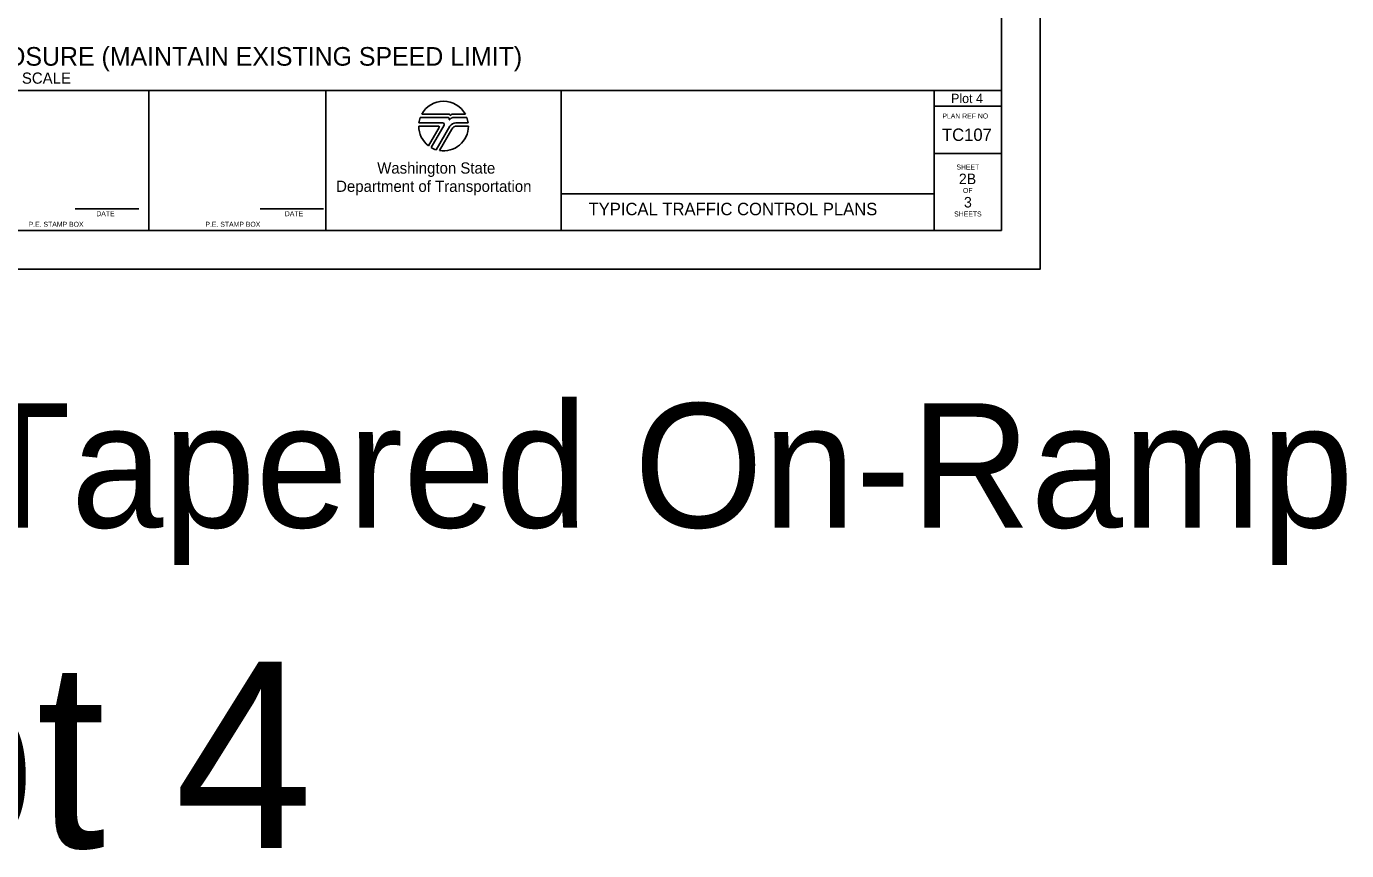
# Model space of a CAD drawing. Extents: x 99999 to 100116, y 99995 to 100013.
# Drawn here: x 100067.9 to 100078.53, y 99995.01 to 100001.64 of the extents above; entities that cross this region are included whole.
import ezdxf

# ---------------------------------------------------------------- set-up
doc = ezdxf.new("R2010")
doc.units = 0
for name, color, linetype in [('SH_DE_DetailHeading1Text', 7, 'Continuous'), ('SH_GI_PlotLimits', 7, 'Continuous'), ('SH_GI_SheetBorder', 7, 'Continuous'), ('SH_GI_SheetLocationText', 7, 'Continuous'), ('SH_GI_SheetTextInCells', 7, 'Continuous'), ('SH_GI_TitleBlockText', 7, 'Continuous'), ('SH_GI_WSDOTLogo', 7, 'Continuous')]:
    doc.layers.add(name, color=color, linetype=linetype)

msp = doc.modelspace()

# ---------------------------------------------------------------- linework, layer by layer
at = {"layer": 'SH_GI_PlotLimits'}
msp.add_lwpolyline([(100059.062, 99999.687), (100076.062, 99999.687), (100076.062, 100010.687), (100059.062, 100010.687)], close=True, dxfattribs=at)
at = {"layer": 'SH_GI_SheetBorder'}
for p, q in [((100075.75, 100010.375), (100075.75, 100000)), ((100060, 100001.126), (100075.75, 100001.126)), ((100068.883, 100000), (100068.883, 100001.126)), ((100070.309, 100001.126), (100070.309, 100000)), ((100072.205, 100001.126), (100072.205, 100000)), ((100075.208, 100001.126), (100075.208, 100000)), ((100075.208, 100001.001), (100075.75, 100001.001)), ((100075.208, 100000.618), (100075.75, 100000.618)), ((100072.205, 100000.295), (100075.208, 100000.295)), ((100068.29, 100000.173), (100068.802, 100000.173)), ((100069.78, 100000.173), (100070.291, 100000.173)), ((100060, 100000), (100075.75, 100000))]:
    msp.add_line(p, q, dxfattribs=at)
at = {"layer": 'SH_GI_WSDOTLogo'}
for p, q in [((100071.303, 100000.935), (100071.081, 100000.935)), ((100071.433, 100000.935), (100071.335, 100000.935)), ((100071.057, 100000.84), (100071.215, 100000.84)), ((100071.059, 100000.866), (100071.25, 100000.866)), ((100071.289, 100000.909), (100071.07, 100000.909)), ((100071.222, 100000.828), (100071.136, 100000.681)), ((100071.261, 100000.846), (100071.157, 100000.667)), ((100071.199, 100000.649), (100071.309, 100000.839)), ((100071.445, 100000.909), (100071.343, 100000.909)), ((100071.343, 100000.909), (100071.343, 100000.909)), ((100071.356, 100000.866), (100071.456, 100000.866)), ((100071.365, 100000.839), (100071.457, 100000.839)), ((100071.224, 100000.643), (100071.324, 100000.816))]:
    msp.add_line(p, q, dxfattribs=at)
for centre, radius, start, end in [((100071.257, 100000.84), 0.2, 28.4787, 151.532), ((100071.303, 100000.926), 0.00903, 329.8742, 90.0033), ((100071.335, 100000.907), 0.0287, 90.0072, 148.1676), ((100071.257, 100000.84), 0.2, 179.9986, 232.8433), ((100071.257, 100000.84), 0.2, 159.696, 172.5057), ((100071.215, 100000.832), 0.0082, 329.7436, 90), ((100071.257, 100000.84), 0.2, 260.5455, 359.8086), ((100071.25, 100000.853), 0.0131, 329.7683, 90), ((100071.289, 100000.895), 0.0148, 327.8418, 89.9985), ((100071.343, 100000.861), 0.0484, 89.9953, 147.8238), ((100071.356, 100000.812), 0.0542, 90, 149.9974), ((100071.365, 100000.792), 0.0476, 90, 150.0543), ((100071.257, 100000.84), 0.2, 7.4943, 20.2941), ((100071.257, 100000.84), 0.2, 239.7929, 253.0448)]:
    msp.add_arc(centre, radius, start, end, dxfattribs=at)

# ---------------------------------------------------------------- texts
at = {"layer": 'SH_DE_DetailHeading1Text'}
for s, height, p in [('FREEWAY (2+ LANES): SINGLE RIGHT LANE CLOSURE (MAINTAIN EXISTING SPEED LIMIT)', 0.15, (100063.191, 100001.326)), ('NOT TO SCALE', 0.09, (100067.373, 100001.181))]:
    msp.add_text(s, height=height, rotation=360, dxfattribs=at).set_placement(p)
at = {"layer": 'SH_GI_SheetBorder'}
msp.add_text('PLAN REF NO', height=0.04003, dxfattribs=at).set_placement((100075.275, 100000.901))
at = {"layer": 'SH_GI_SheetLocationText'}
for s, height, p in [('Plot 4', 0.075, (100075.345, 100001.025)), ('Right Ramps: Tapered On-Ramp', 1, (100058.967, 99997.607)), ('Plot 4', 1.5, (100065.077, 99995.027))]:
    msp.add_text(s, height=height, dxfattribs=at).set_placement(p)
at = {"layer": 'SH_GI_SheetTextInCells'}
for s, height, p in [('Washington State', 0.09007, (100070.723, 100000.457)), ('SHEET', 0.04, (100075.388, 100000.49)), ('Department of Transportation', 0.09007, (100070.392, 100000.31)), ('OF', 0.04, (100075.441, 100000.301)), ('DATE', 0.04, (100068.46, 100000.114)), ('DATE', 0.04, (100069.979, 100000.114)), ('SHEETS', 0.04, (100075.37, 100000.112)), ('P.E. STAMP BOX', 0.04003, (100067.915, 100000.029)), ('P.E. STAMP BOX', 0.04003, (100069.339, 100000.029))]:
    msp.add_text(s, height=height, dxfattribs=at).set_placement(p)
at = {"layer": 'SH_GI_TitleBlockText'}
for s, height, p in [('TC107', 0.1, (100075.272, 100000.72)), ('2B', 0.085, (100075.408, 100000.372)), ('TYPICAL TRAFFIC CONTROL PLANS', 0.1, (100072.425, 100000.122)), ('3', 0.085, (100075.449, 100000.184))]:
    msp.add_text(s, height=height, dxfattribs=at).set_placement(p)

doc.saveas('drawing.dxf')
